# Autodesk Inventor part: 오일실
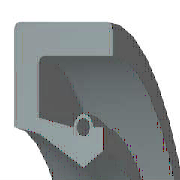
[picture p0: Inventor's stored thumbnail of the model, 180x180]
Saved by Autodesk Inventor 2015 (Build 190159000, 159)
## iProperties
IsCustomPart: 0
Created: 2009-02
Part Number: 오일실
Material: 고무
Description: 오일-실
Document SubType Name: Modeling
Standard: KS B 2804
Standards Organization: KS
Language: ko-KR
Size Designation: S - 17 30 8
Categories: <MemberInstance><Categories><Category DisplayName="샤프트 부품" InternalName="7f7aeb1f-a693-4053-b835-cee3144e0d98" Mnemonic="SHFT"><Category DisplayName="실링" Intern
Density: 0.93 g/cm^3
Appearance: 고무 - 검은색 - 버전 1.1
Author: pww
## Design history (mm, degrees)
revolve "본체" stored, may be unused: angle "d17" = 90 deg
revolve "스프링1" stored, may be unused: angle "d18" = 90 deg
body "Solid1"
sketch "스케치1"
  geometry: L1 (0, 15)-(8, 15); L2 (8, 15)-(8, 13.75); L3 (8, 13.75)-(1.75, 13.75); L4 (0, 15)-(0, 10.6); L5 (0, 10.6)-(1.75, 10.25); L6 (1.75, 10.25)-(4.9, 8.5); L7 (4.9, 8.5)-(0, 8.5); L8 (6.3, 9.375)-(6.3, 10.6); L9 (0, 0)-(9.586, 0) reference; L10 (4.9, 8.5)-(6.3, 9.375); L11 (0, 18)-(0, -3) reference; L12 (-1.917, 0)-(11.503, 0) reference; L13 (4.2, 10.6)-(1.75, 11.09); L14 (1.75, 11.09)-(1.75, 13.75); L15 (6.3, 10.6)-(5.6, 10.6); C1 r 0.455 at (4.9, 10.6); A1 r 0.7 centre (4.9, 10.6) between (5.6, 10.6) and (4.2, 10.6)
  constraints: 26 end point, 5 horizontal alignment, 4 perpendicular, 2 centre point, 2 collinear, 2 horizontal, 2 parallel, 2 point on circle, 2 point on line, 2 vertical alignment, 1 coincident
  dimensions: "d0" = 30 diameter of L1 L9 (= SD2); "d1" = 18.75 diameter of L8.start L9 (= ABDM); "d2" = 1.25 distance of L1.end L2.end (computed from SD); "d3" = 0.91 diameter of C1 (= SPDI); "d4" = 1.4 diameter of A1 (= SPDA); "d5" = 17 diameter of L6.end L9 (= NND); "d6" = 20.5 diameter of L5.end L9 (= TKDM); "d7" = 21.2 diameter of L4.end L9 (= HLDM); "d8" = 4.9 distance from line of C1.centre L4 (= SPDST); "d9" = 6.3 distance between parallel lines of L8 L4 (= SDI); "d10" = 8 distance between parallel lines of L2 L4 (= SWDT); "d12" = 1.75 distance between parallel lines of L14 L4 (= SD)
fillet "모깎기1" dims "d11" = 0.3 (= RR)
other parameters: "SD2" = 30 [user parameter; used in 1 equation term], "SWDT" = 8 [user parameter; used in 1 equation term], "RR" = 0.3 [user parameter; used in 1 equation term], "SD" = 1.75 [user parameter; used in 2 equation terms], "NND" = 17 [user parameter; used in 1 equation term], "SPDA" = 1.4 [user parameter; used in 1 equation term], "SPDI" = 0.91 [user parameter; used in 1 equation term], "TKDM" = 20.5 [user parameter; used in 1 equation term], "HLDM" = 21.2 [user parameter; used in 1 equation term], "ABDM" = 18.75 [user parameter; used in 1 equation term], "SDI" = 6.3 [user parameter; used in 1 equation term], "SPDST" = 4.9 [user parameter; used in 1 equation term], "d13" = 0, "d14" = 0, "d15" = 0, "LAB" = 0.35 [user parameter]
